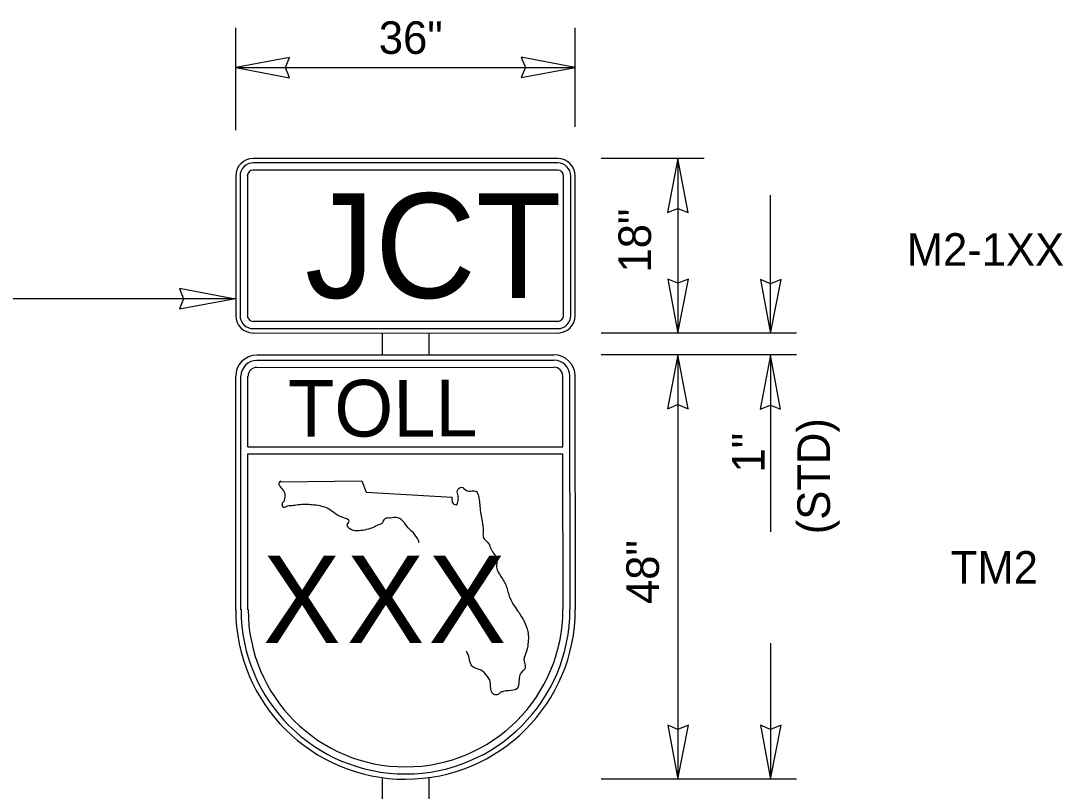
# Model space of a CAD drawing. Extents: x 52649 to 53276, y 9410 to 9805.
# Drawn here: x 52924.3 to 53008.4, y 9726.9 to 9789 of the extents above; entities that cross this region are included whole.
import ezdxf

# ---------------------------------------------------------------- set-up
doc = ezdxf.new("R2010")
doc.units = 0
for name, color, linetype in [('1', 7, 'Continuous'), ('DimLines_dp', 7, 'Continuous'), ('SignPanel', 7, 'Continuous')]:
    doc.layers.add(name, color=color, linetype=linetype)

msp = doc.modelspace()

# ---------------------------------------------------------------- linework, layer by layer
at = {"layer": '1'}
for p, q in [((52953.512, 9762.083), (52953.512, 9763.843)), ((52957.262, 9762.086), (52957.262, 9763.842)), ((52953.512, 9723.703), (52953.513, 9727.947)), ((52957.262, 9723.703), (52957.263, 9727.95))]:
    msp.add_line(p, q, dxfattribs=at)
at = {"layer": 'DimLines_dp'}
for p, q in [((52941.668, 9780.207), (52941.668, 9788.443)), ((52969.042, 9780.459), (52969.042, 9788.443)), ((52946.018, 9786.069), (52941.668, 9785.259)), ((52946.018, 9786.069), (52941.668, 9785.259)), ((52945.688, 9785.259), (52946.018, 9786.069)), ((52945.688, 9785.259), (52946.018, 9786.069)), ((52969.042, 9785.259), (52964.692, 9786.099)), ((52964.692, 9786.099), (52965.022, 9785.259)), ((52941.668, 9785.259), (52969.042, 9785.259)), ((52941.668, 9785.259), (52946.018, 9784.419)), ((52941.668, 9785.259), (52946.018, 9784.419)), ((52946.018, 9784.419), (52945.688, 9785.259)), ((52946.018, 9784.419), (52945.688, 9785.259)), ((52965.022, 9785.259), (52964.692, 9784.449)), ((52964.692, 9784.449), (52969.042, 9785.259)), ((52979.438, 9777.915), (52971.142, 9777.915)), ((52977.324, 9777.915), (52976.484, 9773.565)), ((52977.324, 9777.915), (52976.484, 9773.565)), ((52977.324, 9777.915), (52977.324, 9763.841)), ((52978.134, 9773.565), (52977.324, 9777.915)), ((52978.134, 9773.565), (52977.324, 9777.915)), ((52984.792, 9763.801), (52984.792, 9774.969)), ((52976.484, 9773.565), (52977.324, 9773.895)), ((52976.484, 9773.565), (52977.324, 9773.895)), ((52977.324, 9773.895), (52978.134, 9773.565)), ((52977.324, 9773.895), (52978.134, 9773.565)), ((52941.482, 9766.603), (52937.132, 9767.443)), ((52937.132, 9767.443), (52937.462, 9766.603)), ((52977.324, 9767.861), (52976.514, 9768.191)), ((52976.514, 9768.191), (52977.324, 9763.841)), ((52977.324, 9767.861), (52976.514, 9768.191)), ((52976.514, 9768.191), (52977.324, 9763.841)), ((52977.324, 9763.841), (52978.164, 9768.191)), ((52978.164, 9768.191), (52977.324, 9767.861)), ((52977.324, 9763.841), (52978.164, 9768.191)), ((52978.164, 9768.191), (52977.324, 9767.861)), ((52984.792, 9767.821), (52983.982, 9768.151)), ((52983.982, 9768.151), (52984.792, 9763.801)), ((52984.792, 9763.801), (52985.632, 9768.151)), ((52985.632, 9768.151), (52984.792, 9767.821)), ((52941.668, 9766.603), (52867.415, 9766.603)), ((52937.462, 9766.603), (52937.132, 9765.793)), ((52937.132, 9765.793), (52941.482, 9766.603)), ((52986.87, 9763.841), (52971.142, 9763.841)), ((52986.87, 9762.091), (52971.142, 9762.091)), ((52977.324, 9762.091), (52976.484, 9757.741)), ((52977.324, 9762.091), (52976.484, 9757.741)), ((52977.324, 9762.091), (52977.324, 9727.863)), ((52978.134, 9757.741), (52977.324, 9762.091)), ((52978.134, 9757.741), (52977.324, 9762.091)), ((52984.792, 9762.051), (52983.952, 9757.701)), ((52984.792, 9762.051), (52984.792, 9747.811)), ((52985.602, 9757.701), (52984.792, 9762.051)), ((52976.484, 9757.741), (52977.324, 9758.071)), ((52976.484, 9757.741), (52977.324, 9758.071)), ((52977.324, 9758.071), (52978.134, 9757.741)), ((52977.324, 9758.071), (52978.134, 9757.741)), ((52983.952, 9757.701), (52984.792, 9758.031)), ((52984.792, 9758.031), (52985.602, 9757.701)), ((52984.792, 9738.825), (52984.792, 9727.863)), ((52977.324, 9731.883), (52976.514, 9732.213)), ((52976.514, 9732.213), (52977.324, 9727.863)), ((52977.324, 9731.883), (52976.514, 9732.213)), ((52976.514, 9732.213), (52977.324, 9727.863)), ((52977.324, 9727.863), (52978.164, 9732.213)), ((52978.164, 9732.213), (52977.324, 9731.883)), ((52977.324, 9727.863), (52978.164, 9732.213)), ((52978.164, 9732.213), (52977.324, 9731.883)), ((52984.792, 9731.883), (52983.982, 9732.213)), ((52983.982, 9732.213), (52984.792, 9727.863)), ((52984.792, 9731.883), (52983.982, 9732.213)), ((52983.982, 9732.213), (52984.792, 9727.863)), ((52984.792, 9727.863), (52985.632, 9732.213)), ((52985.632, 9732.213), (52984.792, 9731.883)), ((52984.792, 9727.863), (52985.632, 9732.213)), ((52985.632, 9732.213), (52984.792, 9731.883)), ((52986.87, 9727.863), (52971.142, 9727.863))]:
    msp.add_line(p, q, dxfattribs=at)
at = {"layer": 'SignPanel'}
for p, q in [((52967.63, 9777.913), (52943.076, 9777.921)), ((52967.63, 9777.565), (52943.076, 9777.573)), ((52967.63, 9776.967), (52943.076, 9776.975)), ((52941.668, 9776.509), (52941.668, 9765.247)), ((52942.028, 9776.509), (52942.028, 9765.247)), ((52942.612, 9776.509), (52942.612, 9765.247)), ((52968.098, 9765.247), (52968.098, 9776.509)), ((52968.682, 9765.247), (52968.682, 9776.509)), ((52969.042, 9765.247), (52969.042, 9776.509)), ((52943.076, 9764.793), (52967.63, 9764.785)), ((52943.076, 9764.207), (52967.63, 9764.199)), ((52943.076, 9763.847), (52967.63, 9763.839)), ((52943.384, 9762.077), (52967.326, 9762.093)), ((52943.384, 9761.647), (52967.326, 9761.663)), ((52943.384, 9761.069), (52967.326, 9761.087)), ((52941.668, 9741.533), (52941.668, 9760.361)), ((52942.096, 9741.533), (52942.096, 9760.361)), ((52942.658, 9754.651), (52942.658, 9760.361)), ((52968.052, 9754.667), (52968.052, 9760.377)), ((52968.628, 9741.551), (52968.614, 9760.377)), ((52969.058, 9741.551), (52969.042, 9760.377)), ((52942.658, 9754.651), (52968.052, 9754.667)), ((52942.658, 9754.091), (52968.052, 9754.107)), ((52942.658, 9741.533), (52942.658, 9754.091)), ((52968.068, 9741.551), (52968.052, 9754.107)), ((52945.25, 9751.847), (52951.85, 9751.913)), ((52951.85, 9751.913), (52952.194, 9751.005)), ((52952.194, 9751.005), (52959.11, 9750.609))]:
    msp.add_line(p, q, dxfattribs=at)
for centre, radius, start, end in [((52943.075, 9776.504), 1.407, 90, 180), ((52943.075, 9776.504), 1.055, 90, 180), ((52967.63, 9776.504), 1.407, 0, 90), ((52967.63, 9776.504), 1.055, 0, 90), ((52943.075, 9776.504), 0.469, 90, 180), ((52967.63, 9776.504), 0.469, 0, 90), ((52943.075, 9765.251), 1.407, 180, 270), ((52943.075, 9765.251), 1.055, 180, 270), ((52943.075, 9765.251), 0.469, 180, 270), ((52967.63, 9765.251), 1.407, 270, 360), ((52967.63, 9765.251), 1.055, 270, 360), ((52967.63, 9765.251), 0.469, 270, 360), ((52943.378, 9760.355), 1.711, 90.03983, 180.01899), ((52943.378, 9760.355), 1.283, 90.03983, 180.01899), ((52967.322, 9760.372), 1.711, 0.03983, 90.03983), ((52967.322, 9760.372), 1.283, 0.03983, 90.03983), ((52943.378, 9760.355), 0.713, 90.03983, 180.01899), ((52967.322, 9760.372), 0.713, 0.03983, 90.03983), ((52955.36, 9741.546), 13.686, 180.03983, 0.03983), ((52955.36, 9741.546), 13.258, 180.03983, 0.03983), ((52955.36, 9741.546), 12.688, 180.03983, 0.03983)]:
    msp.add_arc(centre, radius, start, end, dxfattribs=at)
for points in [[(52945.594, 9750.311), (52945.66, 9750.707), (52945.612, 9751.021), (52945.298, 9751.417), (52945.166, 9751.681), (52945.298, 9751.913)], [(52945.594, 9750.311), (52945.66, 9750.707), (52945.612, 9751.021), (52945.298, 9751.417), (52945.166, 9751.681), (52945.298, 9751.913)], [(52959.11, 9750.609), (52959.11, 9750.329), (52959.256, 9750.047), (52959.454, 9749.999), (52959.604, 9750.329), (52959.604, 9750.707), (52959.554, 9751.153), (52959.868, 9751.417), (52960.264, 9751.153), (52961.072, 9751.055), (52961.236, 9750.691), (52961.386, 9749.585), (52961.534, 9748.679), (52961.618, 9747.821), (52961.632, 9747.391), (52962.062, 9746.863), (52962.26, 9746.401), (52962.706, 9745.593), (52962.706, 9744.949), (52963.052, 9744.207), (52963.48, 9743.431), (52963.762, 9742.507), (52964.126, 9741.831), (52964.488, 9741.319), (52964.918, 9740.593), (52965.214, 9739.769), (52965.214, 9738.629), (52965.032, 9737.937), (52964.918, 9737.639), (52964.984, 9737.129), (52964.984, 9736.765), (52964.768, 9736.535), (52964.588, 9736.271), (52964.504, 9735.743), (52964.338, 9735.149), (52963.696, 9734.999), (52963.234, 9734.933), (52962.986, 9734.835), (52962.754, 9734.669), (52962.376, 9734.785), (52962.226, 9735.197), (52962.178, 9735.743), (52961.848, 9736.303), (52961.302, 9736.715), (52960.958, 9736.831), (52960.66, 9737.079), (52960.496, 9737.657), (52960.28, 9738.185)], [(52959.11, 9750.609), (52959.11, 9750.329), (52959.256, 9750.047), (52959.454, 9749.999), (52959.604, 9750.329), (52959.604, 9750.707), (52959.554, 9751.153), (52959.868, 9751.417), (52960.264, 9751.153), (52961.072, 9751.055), (52961.236, 9750.691), (52961.386, 9749.585), (52961.534, 9748.679), (52961.618, 9747.821), (52961.632, 9747.391), (52962.062, 9746.863), (52962.26, 9746.401), (52962.706, 9745.593), (52962.706, 9744.949), (52963.052, 9744.207), (52963.48, 9743.431), (52963.762, 9742.507), (52964.126, 9741.831), (52964.488, 9741.319), (52964.918, 9740.593), (52965.214, 9739.769), (52965.214, 9738.629), (52965.032, 9737.937), (52964.918, 9737.639), (52964.984, 9737.129), (52964.984, 9736.765), (52964.768, 9736.535), (52964.588, 9736.271), (52964.504, 9735.743), (52964.338, 9735.149), (52963.696, 9734.999), (52963.234, 9734.933), (52962.986, 9734.835), (52962.754, 9734.669), (52962.376, 9734.785), (52962.226, 9735.197), (52962.178, 9735.743), (52961.848, 9736.303), (52961.302, 9736.715), (52960.958, 9736.831), (52960.66, 9737.079), (52960.496, 9737.657), (52960.28, 9738.185)], [(52956.47, 9746.929), (52956.122, 9747.573), (52955.578, 9748.133), (52955.15, 9748.679), (52954.604, 9748.975), (52954.174, 9748.925), (52953.812, 9748.909), (52953.614, 9748.777), (52953.448, 9748.481), (52953.218, 9748.381), (52952.69, 9748.133), (52952.048, 9747.953), (52951.454, 9747.887), (52950.874, 9748.051), (52950.662, 9748.349), (52950.808, 9748.661), (52950.248, 9748.991), (52949.044, 9749.717), (52947.838, 9749.981), (52946.716, 9749.981), (52946.188, 9749.915), (52945.858, 9749.883), (52945.514, 9749.783), (52945.43, 9750.065), (52945.594, 9750.311)], [(52956.47, 9746.929), (52956.122, 9747.573), (52955.578, 9748.133), (52955.15, 9748.679), (52954.604, 9748.975), (52954.174, 9748.925), (52953.812, 9748.909), (52953.614, 9748.777), (52953.448, 9748.481), (52953.218, 9748.381), (52952.69, 9748.133), (52952.048, 9747.953), (52951.454, 9747.887), (52950.874, 9748.051), (52950.662, 9748.349), (52950.808, 9748.661), (52950.248, 9748.991), (52949.044, 9749.717), (52947.838, 9749.981), (52946.716, 9749.981), (52946.188, 9749.915), (52945.858, 9749.883), (52945.514, 9749.783), (52945.43, 9750.065), (52945.594, 9750.311)]]:
    msp.add_spline(points, degree=3, dxfattribs=at)

# ---------------------------------------------------------------- texts
at = {"layer": 'DimLines_dp'}
for s, p in [('36"', (52953.209, 9786.353)), ('M2-1XX', (52995.77, 9769.268)), ('TM2', (52999.321, 9743.629))]:
    msp.add_text(s, height=2.625, dxfattribs=at).set_placement(p)
for s, p in [('18"', (52975.153, 9768.723)), ('(STD)', (52989.579, 9747.616)), ('1"', (52984.303, 9752.594)), ('48"', (52975.789, 9741.99))]:
    msp.add_text(s, height=2.625, rotation=90, dxfattribs=at).set_placement(p)
at = {"layer": 'SignPanel'}
msp.add_text('JCT', height=8.4386, dxfattribs=at).set_placement((52947.245, 9766.673))
for s, height, rotation, p in [('TOLL', 4.5708, 0.03983, (52945.887, 9755.489)), ('X', 7.036, 0.04985, (52943.861, 9738.841)), ('X', 7.036, 0.04985, (52950.613, 9738.841)), ('X', 7.036, 0.04985, (52957.2, 9738.841))]:
    msp.add_text(s, height=height, rotation=rotation, dxfattribs=at).set_placement(p)

doc.saveas('drawing.dxf')
